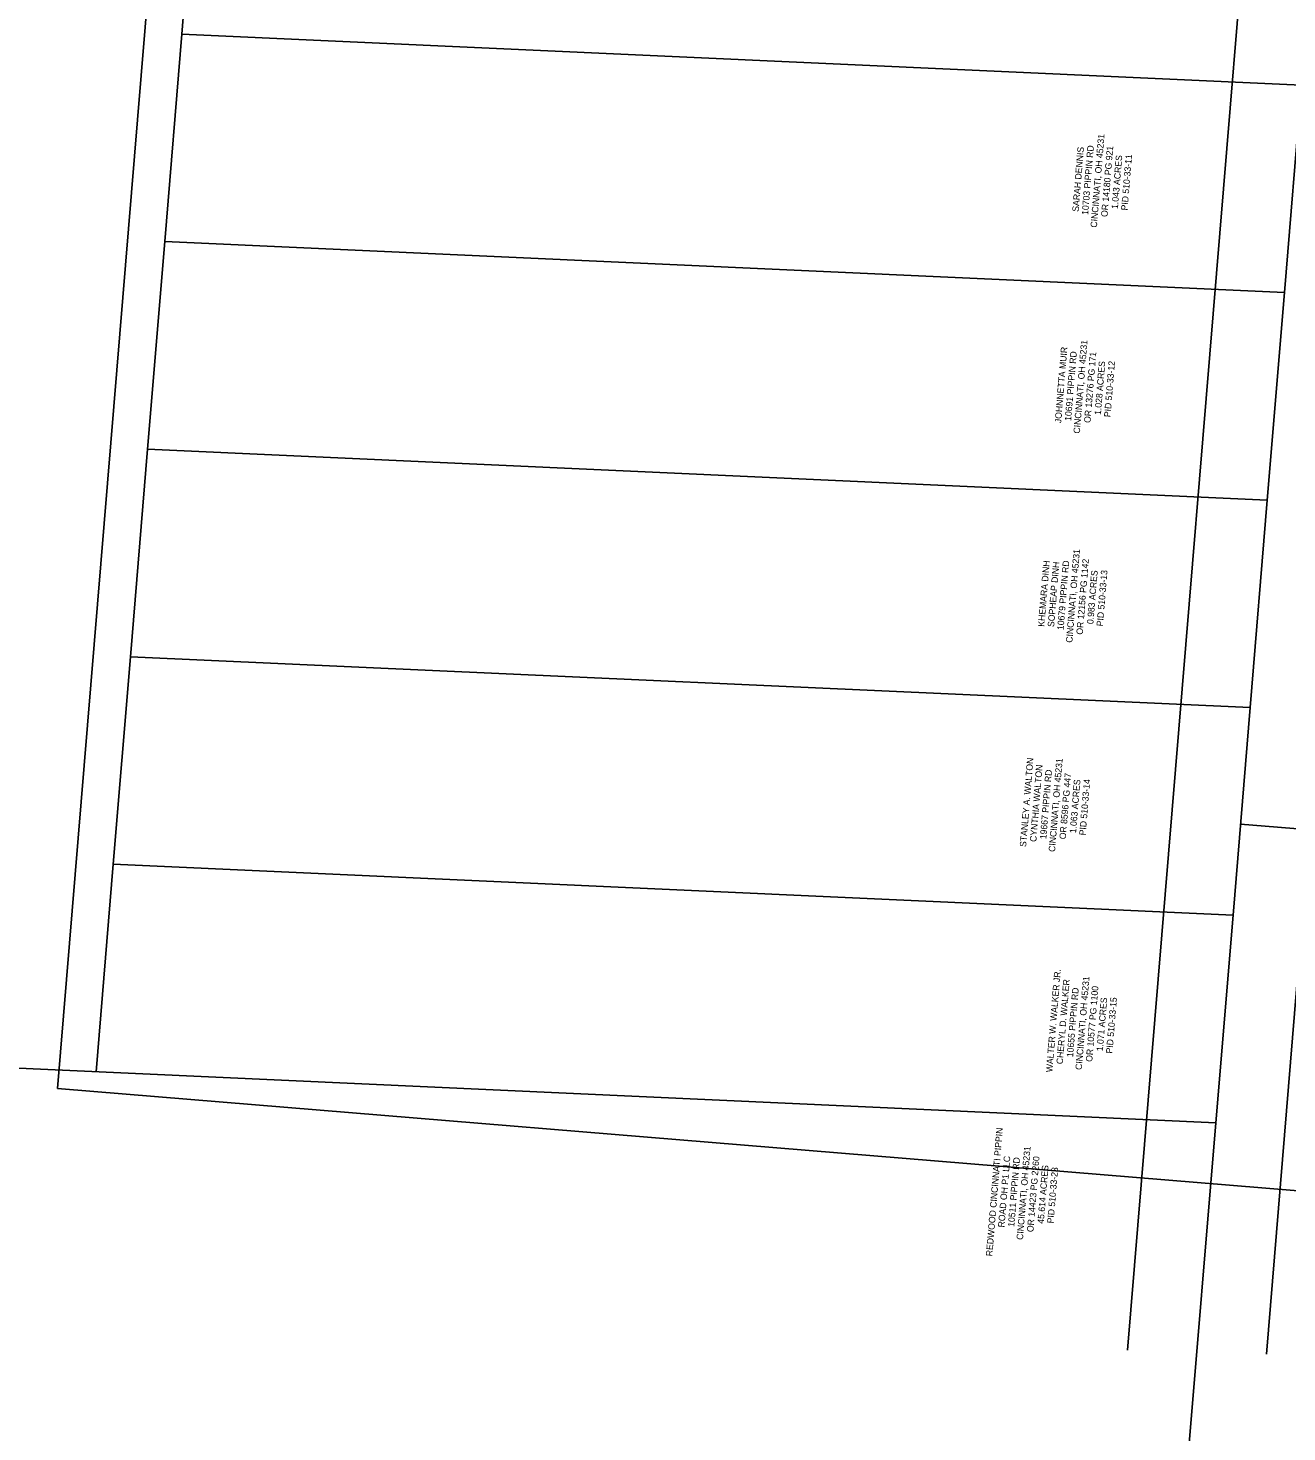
# Model space of a CAD drawing. Extents: x 1379776 to 1382941, y 467490 to 471592.
# Drawn here: x 1381007 to 1381551, y 468891 to 469498 of the extents above; entities that cross this region are included whole.
import ezdxf

# ---------------------------------------------------------------- set-up
doc = ezdxf.new("R2010")
doc.units = 0
for name, color, linetype in [('DR_X_Text', 7, 'Continuous'), ('PV_P_Drive', 7, 'Continuous'), ('PV_X_Driveway', 7, 'Continuous'), ('RC_X_Text', 7, 'Continuous'), ('RD_X_Wall', 7, 'Continuous'), ('SH_Named_Boundary', 7, 'Continuous')]:
    doc.layers.add(name, color=color, linetype=linetype)

msp = doc.modelspace()

# ---------------------------------------------------------------- linework, layer by layer
at = {"layer": 'DR_X_Text'}
msp.add_line((1381530.8, 469154.06), (1381600.93, 469148.27), dxfattribs=at)
at = {"layer": 'PV_P_Drive'}
for p, q in [((1381080.78, 469585.21), (1381073.36, 469495.51)), ((1381073.36, 469495.51), (1381065.95, 469405.82)), ((1381073.36, 469495.51), (1381557.19, 469473.48)), ((1381557.19, 469473.48), (1381549.78, 469383.79)), ((1381065.95, 469405.82), (1381058.54, 469316.12)), ((1381065.95, 469405.82), (1381549.78, 469383.79)), ((1381549.78, 469383.79), (1381542.37, 469294.09)), ((1381058.54, 469316.12), (1381051.13, 469226.43)), ((1381058.54, 469316.12), (1381542.37, 469294.09)), ((1381542.37, 469294.09), (1381534.96, 469204.4)), ((1381051.13, 469226.43), (1381043.72, 469136.73)), ((1381534.96, 469204.4), (1381051.13, 469226.43)), ((1381534.96, 469204.4), (1381527.55, 469114.7)), ((1381043.72, 469136.73), (1381036.31, 469047.04)), ((1381527.55, 469114.7), (1381043.72, 469136.73)), ((1381527.55, 469114.7), (1381520.13, 469025.01)), ((1379794.86, 469103.57), (1381520.13, 469025.01)), ((1381520.13, 469025.01), (1381434.48, 467993.24))]:
    msp.add_line(p, q, dxfattribs=at)
at = {"layer": 'PV_X_Driveway'}
msp.add_lwpolyline([(1381481.91, 468926.74), (1381589.94, 470234.06), (1380557.84, 470275.29)], dxfattribs=at)
at = {"layer": 'RD_X_Wall'}
msp.add_line((1381541.97, 468924.96), (1381557.61, 469114.22), dxfattribs=at)
at = {"layer": 'SH_Named_Boundary'}
msp.add_lwpolyline([(1381019.66, 469039.84), (1381836.87, 468972.31), (1381848.4, 469111.83), (1381859.93, 469251.36), (1381871.46, 469390.88), (1381882.99, 469530.4), (1381894.52, 469669.93), (1381906.05, 469809.45), (1381917.58, 469948.98), (1381929.11, 470088.5), (1381940.64, 470228.03), (1381952.16, 470367.55), (1381134.95, 470435.08), (1381123.42, 470295.56), (1381111.89, 470156.03), (1381100.36, 470016.51), (1381088.83, 469876.98), (1381077.3, 469737.46), (1381065.77, 469597.93), (1381054.24, 469458.41), (1381042.71, 469318.88), (1381031.19, 469179.36)], close=True, dxfattribs=at)

# ---------------------------------------------------------------- texts
at = {"layer": 'RC_X_Text'}
for s, p in [('CINCINNATI, OH 45231', (1381468.71, 469411.79)), ('SARAH DENNIS', (1381460.85, 469418.67)), ('10703 PIPPIN RD', (1381464.95, 469417.27)), ('OR 14180 PG 921', (1381473.3, 469416.39)), ('1.043 ACRES', (1381477.8, 469419.85)), ('PID 510-33-11', (1381481.96, 469419.2)), ('CINCINNATI, OH 45231', (1381461.35, 469322.76)), ('JOHNNETTA MUIR', (1381453.29, 469327.26)), ('10691 PIPPIN RD', (1381457.59, 469328.24)), ('OR 13276 PG 171', (1381465.95, 469327.36)), ('1.028 ACRES', (1381470.45, 469330.82)), ('PID 510-33-12', (1381474.58, 469329.86)), ('CINCINNATI, OH 45231', (1381458.1, 469232.36)), ('KHEMARA DINH', (1381446.02, 469239.28)), ('SOPHEAP DINH', (1381450.23, 469239.15)), ('10679 PIPPIN RD', (1381454.33, 469237.84)), ('OR 12156 PG 1142', (1381462.6, 469235.85)), ('0.983 ACRES', (1381467.19, 469240.42)), ('PID 510-33-13', (1381471.33, 469239.47)), ('STANLEY A. WALTON', (1381438.16, 469144.08)), ('CYNTHIA WALTON', (1381442.55, 469146.27)), ('CINCINNATI, OH 45231', (1381450.63, 469141.96)), ('19667 PIPPIN RD', (1381446.86, 469147.44)), ('OR 8596 PG 447', (1381455.29, 469147.41)), ('1.063 ACRES', (1381459.72, 469150.03)), ('PID 510-33-14', (1381463.86, 469149.1)), ('WALTER W. WALKER JR.', (1381449.48, 469046.71)), ('CINCINNATI, OH 45231', (1381462.2, 469047.72)), ('CHERYL D. WALKER', (1381453.98, 469050.2)), ('10655 PIPPIN RD', (1381458.44, 469053.21)), ('OR 10577 PG 1100', (1381466.71, 469051.21)), ('1.071 ACRES', (1381471.3, 469055.79)), ('PID 510-33-15', (1381475.43, 469054.81)), ('REDWOOD CINCINNATI PIPPIN', (1381423.54, 468967.19)), ('ROAD OH P1 LLC', (1381428.78, 468979.63)), ('10511 PIPPIN RD', (1381433.02, 468979.89)), ('CINCINNATI, OH 45231', (1381436.77, 468974.27)), ('OR 14423 PG 2260', (1381441.26, 468977.61)), ('45.614 ACRES', (1381445.77, 468981.25)), ('PID 510-33-23', (1381450, 468981.38))]:
    msp.add_text(s, height=2.8, rotation=85.27618, dxfattribs=at).set_placement(p)

doc.saveas('drawing.dxf')
